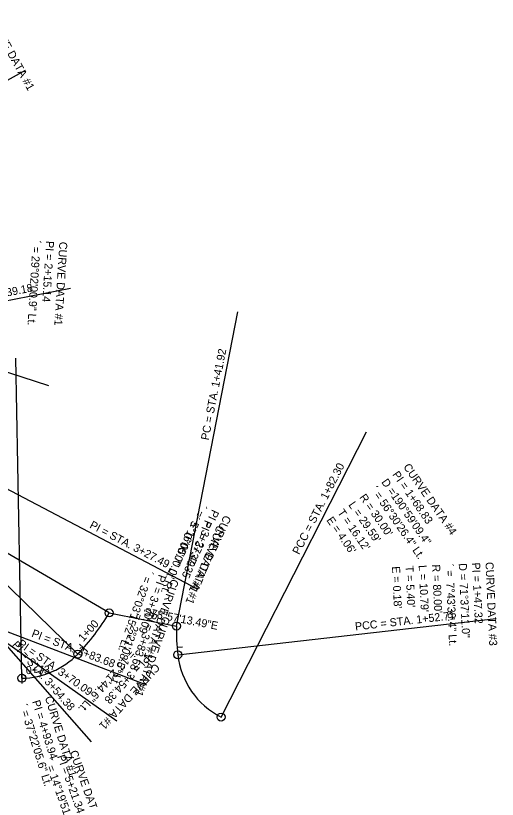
# Model space of a CAD drawing. Extents: x 1158784 to 1165006, y 610007 to 611539.
# Drawn here: x 1163018.2 to 1163198.5, y 610487.8 to 610781.4 of the extents above; entities that cross this region are included whole.
import ezdxf

# ---------------------------------------------------------------- set-up
doc = ezdxf.new("R2010")
doc.units = 0
for name, color, linetype in [('D_Roadway_Centerline', 7, 'Continuous'), ('D_Roadway_Centerline_Bearings', 7, 'Continuous'), ('D_Roadway_Centerline_CurveData', 7, 'Continuous'), ('D_Roadway_Centerline_Flags', 7, 'Continuous'), ('D_Roadway_Centerline_Text', 7, 'Continuous')]:
    doc.layers.add(name, color=color, linetype=linetype)

msp = doc.modelspace()

# ---------------------------------------------------------------- linework, layer by layer
at = {"layer": 'D_Roadway_Centerline'}
msp.add_line((1163053.2, 610557.66), (1163078.4, 610552.74), dxfattribs=at)
for centre, radius, start, end in [((1162984.15, 610598.07), 80, 315.752, 329.6626), ((1163158.38, 610551.02), 80, 178.762, 186.4894), ((1163019.97, 610563.18), 30, 271.0777, 315.752), ((1163108.7, 610545.37), 30, 186.4894, 242.9967)]:
    msp.add_arc(centre, radius, start, end, dxfattribs=at)
at = {"layer": 'D_Roadway_Centerline_Flags'}
for points in [[(1162916.95, 610702.72), (1163021.84, 610761.02)], [(1162916.33, 610679.99), (1163030.44, 610642.86)], [(1162920.92, 610656.39), (1163038.71, 610679.31)], [(1163078.4, 610552.74), (1163101.39, 610670.52)], [(1163020.53, 610533.19), (1163018.27, 610653.17)], [(1163041.46, 610542.25), (1162955.5, 610625.98)], [(1163095.08, 610518.64), (1163149.56, 610625.55)], [(1162980.17, 610622.39), (1163086.39, 610566.56)], [(1163053.2, 610557.66), (1162949.63, 610618.28)], [(1162967.25, 610599.44), (1163046.46, 610509.29)], [(1162958.16, 610586.62), (1163056.06, 610517.22)], [(1162955.09, 610573.54), (1163067.17, 610530.69)], [(1163078.89, 610541.97), (1163198.12, 610555.54)]]:
    msp.add_lwpolyline(points, dxfattribs=at)
for centre in [(1163053.2, 610557.66), (1163078.4, 610552.74), (1163041.46, 610542.25), (1163078.89, 610541.97), (1163020.53, 610533.19), (1163095.08, 610518.64)]:
    msp.add_circle(centre, 1.5, dxfattribs=at)
at = {"layer": 'D_Roadway_Centerline_Text'}
for points in [[(1163042.14, 610545.91), (1163045.12, 610543.23)], [(1163080.62, 610544.83), (1163078.63, 610544.67)], [(1163020.49, 610535.19), (1163020.57, 610531.19)], [(1163020.49, 610535.19), (1163020.57, 610531.19)]]:
    msp.add_lwpolyline(points, dxfattribs=at)

# ---------------------------------------------------------------- texts
at = {"layer": 'D_Roadway_Centerline_Bearings'}
msp.add_text('S78%%d57\'13.49"E', height=3, rotation=348.9537, dxfattribs=at).set_placement((1163066.08, 610556.68))
at = {"layer": 'D_Roadway_Centerline_CurveData'}
for s, rotation, p in [('CURVE DATA #1', 299.0641, (1163007.56, 610780.54)), ('´ = 29%%d02\'00.9" Lt.', 266.4947, (1163024.6, 610697.4)), ('PI = 2+15.14', 266.4947, (1163029.59, 610697.1)), ('CURVE DATA #1', 266.4947, (1163034.58, 610696.79)), ('PI = 1+68.83', 304.743, (1163159.07, 610609.51)), ('CURVE DATA #4', 304.743, (1163163.18, 610612.36)), ('D =190%%d59\'09.4"', 304.743, (1163154.96, 610606.66)), ('´ = 56%%d30\'26.4" Lt.', 304.743, (1163150.85, 610603.81)), ("R = 30.00'", 304.743, (1163146.74, 610600.96)), ("L = 29.59'", 304.743, (1163142.63, 610598.11)), ('´ =  5%%d16\'05.7" Lt.', 244.9054, (1163087.25, 610598.75)), ('PI = 3+27.49', 244.9054, (1163091.78, 610596.63)), ("T = 16.12'", 304.743, (1163138.53, 610595.26)), ('´ =  0%%d00\'00.0" Rt.', 247.5395, (1163084.45, 610594.58)), ('CURVE DATA #1', 244.9054, (1163096.3, 610594.51)), ("E = 4.06'", 304.743, (1163134.42, 610592.41)), ('PI = 3+37.35', 247.5395, (1163089.07, 610592.67)), ('CURVE DATA #1', 247.5395, (1163093.7, 610590.76)), ('´ =  7%%d43\'38.4" Lt.', 272.6257, (1163179.07, 610575.99)), ('D = 71%%d37\'11.0"', 272.6257, (1163184.07, 610576.22)), ('PI = 1+47.32', 272.6257, (1163189.06, 610576.45)), ('CURVE DATA #3', 272.6257, (1163194.06, 610576.68)), ('´ = 32%%d03\'15.2" Lt.', 250.6966, (1163067.08, 610573.9)), ("E = 0.18'", 272.6257, (1163159.09, 610575.07)), ("T = 5.40'", 272.6257, (1163164.09, 610575.3)), ("L = 10.79'", 272.6257, (1163169.08, 610575.53)), ("R = 80.00'", 272.6257, (1163174.08, 610575.76)), ('PI = 3+70.09', 250.6966, (1163071.8, 610572.25)), ('CURVE DATA #1', 250.6966, (1163076.52, 610570.59)), ('´ =  2%%d21\'08.5" Lt.', 250.2559, (1163063.9, 610559.98)), ('PI = 3+83.68', 250.2559, (1163068.61, 610558.3)), ('CURVE DATA #1', 250.2559, (1163073.31, 610556.61)), ('´ = 13%%d21\'44.6" Lt.', 227.9883, (1163062.81, 610545.66)), ('PI = 3+54.38', 227.9883, (1163066.53, 610542.31)), ('CURVE DATA #1', 227.9883, (1163070.24, 610538.96)), ('CURVE DATA #1', 287.2991, (1163029.1, 610525.95)), ('´ = 37%%d22\'05.6" Lt.', 287.2991, (1163019.56, 610522.98)), ('PI = 4+93.94', 287.2991, (1163024.33, 610524.46)), ('CURVE DATA #1', 289.4312, (1163038.39, 610505.56)), ('´ = 14%%d19\'51.6" Lt.', 289.4312, (1163028.96, 610502.24)), ('PI = 5+21.34', 289.4312, (1163033.68, 610503.9))]:
    msp.add_text(s, height=3, rotation=rotation, dxfattribs=at).set_placement(p)
at = {"layer": 'D_Roadway_Centerline_Flags'}
for s, rotation, p in [('PI = STA. 2+39.18', 11.0115, (1162992.39, 610671.82)), ('PC = STA. 1+41.92', 78.9537, (1163090.43, 610622.2)), ('PCC = STA. 1+82.30', 62.9967, (1163124.3, 610579.29)), ('PI = STA. 3+27.49', 332.2712, (1163045.63, 610589.68)), ('PCC = STA. 1+52.71', 6.4894, (1163145.41, 610551.05)), ('PI = STA. 3+83.68', 339.0797, (1163023.9, 610548.84)), ('PI = STA. 3+54.38', 311.3071, (1163016.63, 610545.52)), ('PI = STA. 3+70.09', 324.6695, (1163018.72, 610545.53))]:
    msp.add_text(s, height=3, rotation=rotation, dxfattribs=at).set_placement(p)
at = {"layer": 'D_Roadway_Centerline_Text'}
for s, rotation, p in [('1+00', 48.03, (1163043.52, 610546.69)), ('0+73', 1.0777, (1163022, 610534.72)), ('0+73', 1.0777, (1163022, 610534.72))]:
    msp.add_text(s, height=3, rotation=rotation, dxfattribs=at).set_placement(p)

doc.saveas('drawing.dxf')
